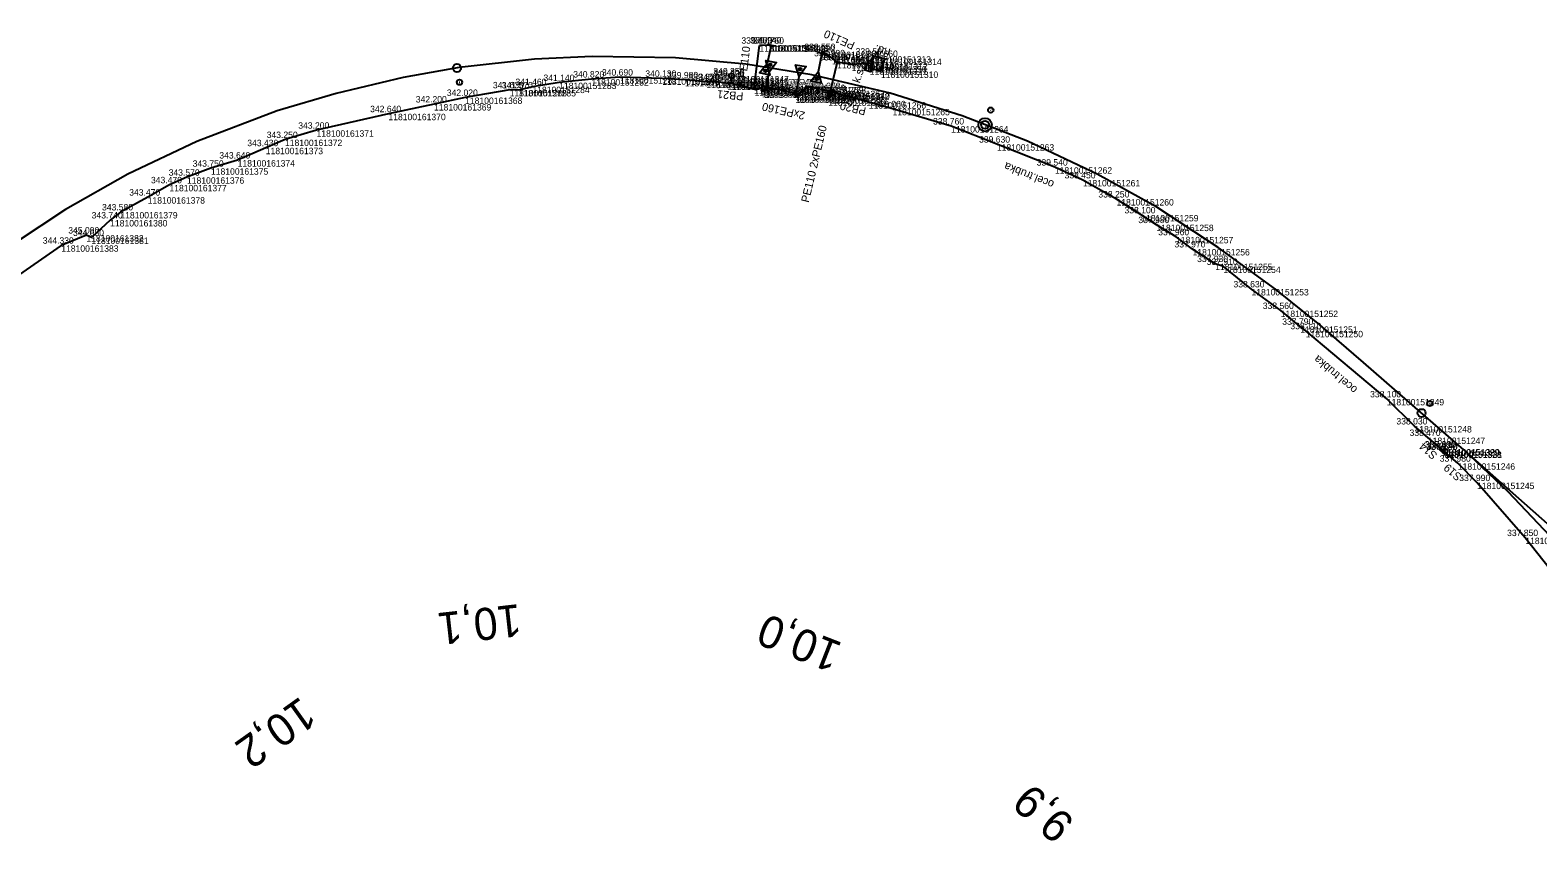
# Model space of a CAD drawing. Extents: x -732194 to -724760, y -944826 to -941477.
# Drawn here: x -726586.2 to -726304.2, y -941987.6 to -941833 of the extents above; entities that cross this region are included whole.
import ezdxf

# ---------------------------------------------------------------- set-up
doc = ezdxf.new("R2010")
doc.units = 0
for name, color, linetype in [('Vrstva 1', 7, 'Continuous'), ('Vrstva 25', 7, 'Continuous'), ('Vrstva 26', 7, 'Continuous'), ('Vrstva 28', 7, 'Continuous'), ('Vrstva 31', 7, 'Continuous'), ('Vrstva 35', 7, 'Continuous'), ('Vrstva 36', 7, 'Continuous'), ('Vrstva 4', 7, 'Continuous'), ('Vrstva 60', 7, 'Continuous'), ('Vrstva 61', 7, 'Continuous'), ('Vrstva 7', 7, 'Continuous')]:
    doc.layers.add(name, color=color, linetype=linetype)

msp = doc.modelspace()

# ---------------------------------------------------------------- linework, layer by layer
at = {"layer": 'Vrstva 1'}
for points in [[(-726318.02, -941911.5), (-726326.6, -941904), (-726336.76, -941895.13), (-726344.93, -941888.1), (-726353.24, -941881.47), (-726363.93, -941873.67), (-726375.42, -941866.09), (-726386.59, -941859.91), (-726399.6, -941853.79), (-726411.82, -941849.03), (-726425.29, -941844.79), (-726440, -941841.35), (-726452.29, -941839.39), (-726465.45, -941838.18), (-726481.04, -941837.9), (-726491.84, -941838.43), (-726505.92, -941840.01), (-726516.42, -941841.85), (-726528.96, -941844.82), (-726540.03, -941848.12), (-726555, -941853.8), (-726567.96, -941859.94), (-726579.57, -941866.53), (-726589.02, -941872.75)], [(-726075.63, -942130.21), (-726101.92, -942107.27), (-726129.96, -942082.52), (-726165.94, -942050.65), (-726201.74, -942019.26), (-726248.07, -941978.65), (-726277.07, -941953.1), (-726291.76, -941938.6), (-726301.83, -941927.65), (-726309.68, -941919.38), (-726318.02, -941911.5), (-726300.8, -941926.68), (-726297.65, -941929.32), (-726289.24, -941936.18), (-726279.87, -941942.93), (-726261.51, -941955.72), (-726252.77, -941962.25), (-726242.17, -941969.3), (-726231.93, -941976.55), (-726224.85, -941981.79)]]:
    msp.add_lwpolyline(points, dxfattribs=at)
at = {"layer": 'Vrstva 25'}
msp.add_lwpolyline([(-726429.37, -941838.61), (-726428.42, -941838.91), (-726429.03, -941840.81), (-726429.98, -941840.51), (-726429.37, -941838.61)], dxfattribs=at)
at = {"layer": 'Vrstva 26'}
msp.add_line((-726437.04, -941844.32), (-726436.9, -941845.95), dxfattribs=at)
for points in [[(-726428.99, -941839.16), (-726432.52, -941839.43), (-726435.24, -941838.97), (-726436.9, -941845.95)], [(-726437.04, -941844.32), (-726440.53, -941843.63), (-726441.06, -941843.62), (-726441.68, -941844.44), (-726442.49, -941845.05), (-726443.08, -941844.83), (-726449.33, -941843.41), (-726449.39, -941843.91), (-726450.69, -941844.08), (-726455, -941842.98), (-726455.75, -941842.95), (-726457.73, -941842.64), (-726459.7, -941842.65), (-726463.7, -941842.31), (-726467.96, -941842.03), (-726475.87, -941841.8), (-726481.19, -941842.16), (-726487.24, -941842.81), (-726492.25, -941843.57), (-726494.81, -941844.2), (-726496.5, -941844.18), (-726504.84, -941845.6), (-726510.65, -941846.83), (-726519.18, -941848.64), (-726532.63, -941851.73), (-726538.53, -941853.47), (-726542.13, -941855), (-726547.39, -941857.31), (-726552.38, -941858.84), (-726556.87, -941860.52), (-726560.15, -941861.94), (-726564.22, -941864.24), (-726569.33, -941867.02), (-726571.24, -941868.52), (-726574.75, -941871.78), (-726575.69, -941871.34), (-726580.39, -941873.25), (-726599.3, -941886.4)]]:
    msp.add_lwpolyline(points, dxfattribs=at)
at = {"layer": 'Vrstva 28'}
for p, q in [((-726455.03, -941841.57), (-726454.93, -941841.57)), ((-726450.78, -941843.7), (-726450.69, -941844.08)), ((-726437.04, -941844.32), (-726436.9, -941845.95)), ((-726436.13, -941844.68), (-726436.03, -941844.7)), ((-726322, -941911.32), (-726321.92, -941911.38)), ((-726321.53, -941911.75), (-726321.61, -941911.84)), ((-726321.57, -941911.72), (-726321.49, -941911.78))]:
    msp.add_line(p, q, dxfattribs=at)
for points in [[(-726450.78, -941843.7), (-726449.77, -941835.84)], [(-726447.59, -941835.85), (-726448.11, -941835.78), (-726449.77, -941835.84)], [(-726438.08, -941837.37), (-726438.01, -941837.02), (-726436.22, -941838.19), (-726435.24, -941838.97)], [(-726428.99, -941839.16), (-726432.52, -941839.43), (-726435.24, -941838.97), (-726436.9, -941845.95)], [(-726437.04, -941844.32), (-726440.53, -941843.63), (-726441.06, -941843.62), (-726441.68, -941844.44), (-726442.49, -941845.05), (-726443.08, -941844.83), (-726449.33, -941843.41), (-726449.39, -941843.91), (-726450.69, -941844.08), (-726455, -941842.98), (-726455.75, -941842.95), (-726457.73, -941842.64), (-726459.7, -941842.65), (-726463.7, -941842.31), (-726467.96, -941842.03), (-726475.87, -941841.8), (-726481.19, -941842.16), (-726487.24, -941842.81), (-726492.25, -941843.57), (-726494.81, -941844.2), (-726496.5, -941844.18), (-726504.84, -941845.6), (-726510.65, -941846.83), (-726519.18, -941848.64), (-726532.63, -941851.73), (-726538.53, -941853.47), (-726542.13, -941855), (-726547.39, -941857.31), (-726552.38, -941858.84), (-726556.87, -941860.52), (-726560.15, -941861.94), (-726564.22, -941864.24), (-726569.33, -941867.02), (-726571.24, -941868.52), (-726574.75, -941871.78), (-726575.69, -941871.34), (-726580.39, -941873.25), (-726599.3, -941886.4)], [(-726455, -941842.98), (-726455.04, -941842.21), (-726454.99, -941841.92), (-726454.98, -941841.57)], [(-726448.57, -941844.25), (-726448.83, -941844.48), (-726449.29, -941844.35), (-726449.39, -941843.91)], [(-726442.49, -941845.05), (-726442.62, -941845.32), (-726443.05, -941845.4), (-726442.89, -941845.07)], [(-726300.83, -941935.1), (-726306.5, -941927.93), (-726315.51, -941917.64), (-726319.12, -941914.01), (-726321.61, -941911.84), (-726322.08, -941911.41), (-726324.72, -941909.2), (-726327.22, -941907.05), (-726332.4, -941901.98), (-726347.57, -941889.24), (-726348.59, -941888.41), (-726352.24, -941885.45), (-726357.72, -941881.42), (-726362.98, -941877.21), (-726364.51, -941876.68), (-726368.75, -941873.94), (-726371.83, -941871.66), (-726375.51, -941869.39), (-726378.35, -941867.57), (-726382.97, -941864.6), (-726389.26, -941861.03), (-726394.51, -941858.63), (-726405.35, -941854.33), (-726413.91, -941850.95), (-726424.87, -941847.72), (-726429.31, -941846.47), (-726437.04, -941844.32)], [(-726436.9, -941845.95), (-726436.41, -941845.56), (-726436.19, -941844.83), (-726436.08, -941844.69)], [(-726322.08, -941911.41), (-726321.96, -941911.35)]]:
    msp.add_lwpolyline(points, dxfattribs=at)
for centre in [(-726454.98, -941841.57), (-726436.08, -941844.69), (-726321.96, -941911.35), (-726321.53, -941911.75)]:
    msp.add_circle(centre, 0.5, dxfattribs=at)
at = {"layer": 'Vrstva 31'}
for points in [[(-726437.04, -941844.32), (-726440.53, -941843.63), (-726441.06, -941843.62), (-726441.68, -941844.44), (-726442.49, -941845.05), (-726443.08, -941844.83), (-726449.33, -941843.41), (-726449.39, -941843.91), (-726450.69, -941844.08), (-726455, -941842.98), (-726455.75, -941842.95), (-726457.73, -941842.64), (-726459.7, -941842.65), (-726463.7, -941842.31), (-726467.96, -941842.03), (-726475.87, -941841.8), (-726481.19, -941842.16), (-726487.24, -941842.81), (-726492.25, -941843.57), (-726494.81, -941844.2), (-726496.5, -941844.18), (-726504.84, -941845.6), (-726510.65, -941846.83), (-726519.18, -941848.64), (-726532.63, -941851.73), (-726538.53, -941853.47), (-726542.13, -941855), (-726547.39, -941857.31), (-726552.38, -941858.84), (-726556.87, -941860.52), (-726560.15, -941861.94), (-726564.22, -941864.24), (-726569.33, -941867.02), (-726571.24, -941868.52), (-726574.75, -941871.78), (-726575.69, -941871.34), (-726580.39, -941873.25), (-726599.3, -941886.4)], [(-726300.83, -941935.1), (-726306.5, -941927.93), (-726315.51, -941917.64), (-726319.12, -941914.01), (-726321.61, -941911.84), (-726322.08, -941911.41), (-726324.72, -941909.2), (-726327.22, -941907.05), (-726332.4, -941901.98), (-726347.57, -941889.24), (-726348.59, -941888.41), (-726352.24, -941885.45), (-726357.72, -941881.42), (-726362.98, -941877.21), (-726364.51, -941876.68), (-726368.75, -941873.94), (-726371.83, -941871.66), (-726375.51, -941869.39), (-726378.35, -941867.57), (-726382.97, -941864.6), (-726389.26, -941861.03), (-726394.51, -941858.63), (-726405.35, -941854.33), (-726413.91, -941850.95), (-726424.87, -941847.72), (-726429.31, -941846.47), (-726437.04, -941844.32)]]:
    msp.add_lwpolyline(points, dxfattribs=at)
at = {"layer": 'Vrstva 35'}
for points in [[(-726450.78, -941843.7), (-726449.77, -941835.84)], [(-726435.24, -941838.97), (-726436.22, -941838.19), (-726438.08, -941837.37)], [(-726435.24, -941838.97), (-726436.9, -941845.95)], [(-726443.08, -941844.83), (-726449.33, -941843.41)], [(-726394.51, -941858.63), (-726405.35, -941854.33)], [(-726332.4, -941901.98), (-726347.57, -941889.24)]]:
    msp.add_lwpolyline(points, dxfattribs=at)
at = {"layer": 'Vrstva 36'}
msp.add_lwpolyline([(-726427.04, -941840.73), (-726429.13, -941840.12), (-726428.41, -941837.87), (-726426.38, -941838.31), (-726427.04, -941840.73)], dxfattribs=at)
at = {"layer": 'Vrstva 4'}
for p, q in [((-726446.83, -941836.02), (-726448.35, -941835.68)), ((-726437.32, -941837.53), (-726438.84, -941837.21)), ((-726448.42, -941840.45), (-726448.84, -941840.71)), ((-726447.95, -941839.62), (-726447.54, -941839.34)), ((-726442.36, -941840.43), (-726441.96, -941840.14)), ((-726438.83, -941841.98), (-726439.24, -941842.25)), ((-726449.34, -941844.11), (-726447.8, -941844.39)), ((-726443.66, -941844.95), (-726442.12, -941845.19))]:
    msp.add_line(p, q, dxfattribs=at)
for points in [[(-726447.59, -941835.85), (-726448.36, -941839.24), (-726447.84, -941841.42), (-726449.79, -941840.98), (-726448.36, -941839.24)], [(-726438.08, -941837.37), (-726438.78, -941840.77), (-726438.22, -941842.94), (-726440.18, -941842.54), (-726438.78, -941840.77)], [(-726448.57, -941844.25), (-726447.95, -941840.83), (-726448.57, -941838.68), (-726446.6, -941839.03), (-726447.95, -941840.83)], [(-726442.89, -941845.07), (-726442.34, -941841.64), (-726443, -941839.5), (-726441.03, -941839.81), (-726442.34, -941841.64)]]:
    msp.add_lwpolyline(points, dxfattribs=at)
for centre in [(-726448.63, -941840.58), (-726447.74, -941839.48), (-726442.16, -941840.29), (-726439.03, -941842.12)]:
    msp.add_circle(centre, 0.248, dxfattribs=at)
at = {"layer": 'Vrstva 60'}
for p, q in [((-726449.77, -941835.84), (-726449.77, -941835.84)), ((-726448.11, -941835.78), (-726448.11, -941835.78)), ((-726447.59, -941835.85), (-726447.59, -941835.85)), ((-726438.08, -941837.37), (-726438.08, -941837.37)), ((-726438.01, -941837.02), (-726438.01, -941837.02)), ((-726436.22, -941838.19), (-726436.22, -941838.19)), ((-726435.24, -941838.97), (-726435.24, -941838.97)), ((-726432.52, -941839.43), (-726432.52, -941839.43)), ((-726429.2, -941839.71), (-726429.2, -941839.71)), ((-726429.13, -941840.12), (-726429.13, -941840.12)), ((-726428.99, -941839.16), (-726428.99, -941839.16)), ((-726428.41, -941837.87), (-726428.41, -941837.87)), ((-726426.38, -941838.31), (-726426.38, -941838.31)), ((-726487.24, -941842.81), (-726487.24, -941842.81)), ((-726481.19, -941842.16), (-726481.19, -941842.16)), ((-726475.87, -941841.8), (-726475.87, -941841.8)), ((-726467.96, -941842.03), (-726467.96, -941842.03)), ((-726463.7, -941842.31), (-726463.7, -941842.31)), ((-726459.7, -941842.65), (-726459.7, -941842.65)), ((-726457.73, -941842.64), (-726457.73, -941842.64)), ((-726455.75, -941842.95), (-726455.75, -941842.95)), ((-726455.04, -941842.21), (-726455.04, -941842.21)), ((-726455, -941842.98), (-726455, -941842.98)), ((-726454.99, -941841.92), (-726454.99, -941841.92)), ((-726454.98, -941841.57), (-726454.98, -941841.57)), ((-726427.04, -941840.73), (-726427.04, -941840.73)), ((-726504.84, -941845.6), (-726504.84, -941845.6)), ((-726496.5, -941844.18), (-726496.5, -941844.18)), ((-726494.81, -941844.2), (-726494.81, -941844.2)), ((-726492.25, -941843.57), (-726492.25, -941843.57)), ((-726450.78, -941843.7), (-726450.78, -941843.7)), ((-726450.69, -941844.08), (-726450.69, -941844.08)), ((-726449.39, -941843.91), (-726449.39, -941843.91)), ((-726449.33, -941843.41), (-726449.33, -941843.41)), ((-726449.29, -941844.35), (-726449.29, -941844.35)), ((-726448.83, -941844.48), (-726448.83, -941844.48)), ((-726448.57, -941844.25), (-726448.57, -941844.25)), ((-726443.08, -941844.83), (-726443.08, -941844.83)), ((-726443.05, -941845.4), (-726443.05, -941845.4)), ((-726442.89, -941845.07), (-726442.89, -941845.07)), ((-726442.62, -941845.32), (-726442.62, -941845.32)), ((-726442.49, -941845.05), (-726442.49, -941845.05)), ((-726441.68, -941844.44), (-726441.68, -941844.44)), ((-726441.06, -941843.62), (-726441.06, -941843.62)), ((-726440.53, -941843.63), (-726440.53, -941843.63)), ((-726437.04, -941844.32), (-726437.04, -941844.32)), ((-726436.9, -941845.95), (-726436.9, -941845.95)), ((-726436.41, -941845.56), (-726436.41, -941845.56)), ((-726436.19, -941844.83), (-726436.19, -941844.83)), ((-726436.08, -941844.69), (-726436.08, -941844.69)), ((-726519.18, -941848.64), (-726519.18, -941848.64)), ((-726510.65, -941846.83), (-726510.65, -941846.83)), ((-726429.31, -941846.47), (-726429.31, -941846.47)), ((-726424.87, -941847.72), (-726424.87, -941847.72)), ((-726532.63, -941851.73), (-726532.63, -941851.73)), ((-726413.91, -941850.95), (-726413.91, -941850.95)), ((-726538.53, -941853.47), (-726538.53, -941853.47)), ((-726405.35, -941854.33), (-726405.35, -941854.33)), ((-726547.39, -941857.31), (-726547.39, -941857.31)), ((-726542.13, -941855), (-726542.13, -941855)), ((-726552.38, -941858.84), (-726552.38, -941858.84)), ((-726394.51, -941858.63), (-726394.51, -941858.63)), ((-726560.15, -941861.94), (-726560.15, -941861.94)), ((-726556.87, -941860.52), (-726556.87, -941860.52)), ((-726389.26, -941861.03), (-726389.26, -941861.03)), ((-726564.22, -941864.24), (-726564.22, -941864.24)), ((-726382.97, -941864.6), (-726382.97, -941864.6)), ((-726571.24, -941868.52), (-726571.24, -941868.52)), ((-726569.33, -941867.02), (-726569.33, -941867.02)), ((-726378.35, -941867.57), (-726378.35, -941867.57)), ((-726575.69, -941871.34), (-726575.69, -941871.34)), ((-726375.51, -941869.39), (-726375.51, -941869.39)), ((-726580.39, -941873.25), (-726580.39, -941873.25)), ((-726574.75, -941871.78), (-726574.75, -941871.78)), ((-726371.83, -941871.66), (-726371.83, -941871.66)), ((-726368.75, -941873.94), (-726368.75, -941873.94)), ((-726364.51, -941876.68), (-726364.51, -941876.68)), ((-726362.98, -941877.21), (-726362.98, -941877.21)), ((-726357.72, -941881.42), (-726357.72, -941881.42)), ((-726352.24, -941885.45), (-726352.24, -941885.45)), ((-726348.59, -941888.41), (-726348.59, -941888.41)), ((-726347.57, -941889.24), (-726347.57, -941889.24)), ((-726332.4, -941901.98), (-726332.4, -941901.98)), ((-726327.22, -941907.05), (-726327.22, -941907.05)), ((-726324.72, -941909.2), (-726324.72, -941909.2)), ((-726322.08, -941911.41), (-726322.08, -941911.41)), ((-726321.96, -941911.35), (-726321.96, -941911.35)), ((-726321.61, -941911.84), (-726321.61, -941911.84)), ((-726321.53, -941911.75), (-726321.53, -941911.75)), ((-726319.12, -941914.01), (-726319.12, -941914.01)), ((-726315.51, -941917.64), (-726315.51, -941917.64)), ((-726306.5, -941927.93), (-726306.5, -941927.93))]:
    msp.add_line(p, q, dxfattribs=at)
at = {"layer": 'Vrstva 7'}
for p, q in [((-726505.94, -941842.74), (-726505.84, -941842.73)), ((-726406.55, -941847.93), (-726406.46, -941847.97)), ((-726324.39, -941902.8), (-726324.31, -941902.86))]:
    msp.add_line(p, q, dxfattribs=at)
for centre, radius in [((-726506.36, -941840.08), 0.75), ((-726505.89, -941842.74), 0.5), ((-726406.51, -941847.95), 0.5), ((-726407.57, -941850.69), 1.25), ((-726407.57, -941850.69), 0.752), ((-726324.35, -941902.83), 0.5), ((-726325.9, -941904.61), 0.75)]:
    msp.add_circle(centre, radius, dxfattribs=at)

# ---------------------------------------------------------------- texts
at = {"layer": 'Vrstva 25'}
msp.add_text('k.s.', height=1.5, rotation=72.2553, dxfattribs=at).set_placement((-726431.01, -941842.99))
at = {"layer": 'Vrstva 28'}
for s, rotation, p in [('PB21', 174.7314, (-726452.72, -941844.67)), ('PB20', 166.8492, (-726429.72, -941847.49)), ('S14', 138.8684, (-726322.83, -941912.32)), ('S19', 138.8684, (-726318.25, -941916.32))]:
    msp.add_text(s, height=1.5, rotation=rotation, dxfattribs=at).set_placement(p)
at = {"layer": 'Vrstva 36'}
for s, rotation, p in [('PE110', 156.2092, (-726431.79, -941835.32)), ('PE110', 82.696, (-726452.24, -941842.08)), ('r.d.', 163.7293, (-726425.17, -941836.53)), ('2xPE160', 167.1997, (-726441.14, -941848.33)), ('PE110 2xPE160', 76.6223, (-726440.55, -941865.34)), ('ocel.trubka', 158.3628, (-726394.52, -941861.3)), ('ocel.trubka', 139.9759, (-726337.78, -941900.01))]:
    msp.add_text(s, height=1.5, rotation=rotation, dxfattribs=at).set_placement(p)
at = {"layer": 'Vrstva 60'}
for s, p in [('118100151327', (-726449.77, -941837.04)), ('118100151349', (-726448.11, -941836.98)), ('118100151348', (-726447.59, -941837.05)), ('118100151319', (-726438.08, -941838.57)), ('118100151318', (-726438.01, -941838.22)), ('118100151317', (-726436.22, -941839.39)), ('118100151316', (-726435.24, -941840.17)), ('118100151315', (-726432.52, -941840.63)), ('118100151350', (-726429.2, -941840.91)), ('118100151311', (-726429.13, -941841.32)), ('118100151312', (-726428.99, -941840.36)), ('118100151313', (-726428.41, -941839.07)), ('118100151314', (-726426.38, -941839.51)), ('118100151283', (-726487.24, -941844.01)), ('118100151282', (-726481.19, -941843.36)), ('118100151281', (-726475.87, -941843)), ('118100151280', (-726467.96, -941843.23)), ('118100151279', (-726463.7, -941843.51)), ('118100151278', (-726459.7, -941843.85)), ('118100151277', (-726457.73, -941843.84)), ('118100151276', (-726455.75, -941844.15)), ('118100151345', (-726455.04, -941843.41)), ('118100151344', (-726455, -941844.18)), ('118100151346', (-726454.99, -941843.12)), ('118100151347', (-726454.98, -941842.77)), ('118100151310', (-726427.04, -941841.93)), ('118100161368', (-726504.84, -941846.8)), ('118100151286', (-726496.5, -941845.38)), ('118100151285', (-726494.81, -941845.4)), ('118100151284', (-726492.25, -941844.77)), ('118100151326', (-726450.78, -941844.9)), ('118100151275', (-726450.69, -941845.28)), ('118100151274', (-726449.39, -941845.11)), ('118100151273', (-726449.33, -941844.61)), ('118100151343', (-726449.29, -941845.55)), ('118100151342', (-726448.83, -941845.68)), ('118100151341', (-726448.57, -941845.45)), ('118100151272', (-726443.08, -941846.03)), ('118100151324', (-726443.05, -941846.6)), ('118100151325', (-726442.89, -941846.27)), ('118100151323', (-726442.62, -941846.52)), ('118100151271', (-726442.49, -941846.25)), ('118100151270', (-726441.68, -941845.64)), ('118100151269', (-726441.06, -941844.82)), ('118100151268', (-726440.53, -941844.83)), ('118100151267', (-726437.04, -941845.52)), ('118100151320', (-726436.9, -941847.15)), ('118100151321', (-726436.41, -941846.76)), ('118100151322', (-726436.19, -941846.03)), ('118100151340', (-726436.08, -941845.89)), ('118100161370', (-726519.18, -941849.84)), ('118100161369', (-726510.65, -941848.03)), ('118100151266', (-726429.31, -941847.67)), ('118100151265', (-726424.87, -941848.92)), ('118100161371', (-726532.63, -941852.93)), ('118100151264', (-726413.91, -941852.15)), ('118100161372', (-726538.53, -941854.67)), ('118100151263', (-726405.35, -941855.53)), ('118100161374', (-726547.39, -941858.51)), ('118100161373', (-726542.13, -941856.2)), ('118100161375', (-726552.38, -941860.04)), ('118100151262', (-726394.51, -941859.83)), ('118100161377', (-726560.15, -941863.14)), ('118100161376', (-726556.87, -941861.72)), ('118100151261', (-726389.26, -941862.23)), ('118100161378', (-726564.22, -941865.44)), ('118100151260', (-726382.97, -941865.8)), ('118100161380', (-726571.24, -941869.72)), ('118100161379', (-726569.33, -941868.22)), ('118100151259', (-726378.35, -941868.77)), ('118100161382', (-726575.69, -941872.54)), ('118100151258', (-726375.51, -941870.59)), ('118100161383', (-726580.39, -941874.45)), ('118100161381', (-726574.75, -941872.98)), ('118100151257', (-726371.83, -941872.86)), ('118100151256', (-726368.75, -941875.14)), ('118100151255', (-726364.51, -941877.88)), ('118100151254', (-726362.98, -941878.41)), ('118100151253', (-726357.72, -941882.62)), ('118100151252', (-726352.24, -941886.65)), ('118100151251', (-726348.59, -941889.61)), ('118100151250', (-726347.57, -941890.44)), ('118100151249', (-726332.4, -941903.18)), ('118100151248', (-726327.22, -941908.25)), ('118100151247', (-726324.72, -941910.4)), ('118100151329', (-726322.08, -941912.61)), ('118100151330', (-726321.96, -941912.55)), ('118100151328', (-726321.61, -941913.04)), ('118100151331', (-726321.53, -941912.95)), ('118100151246', (-726319.12, -941915.21)), ('118100151245', (-726315.51, -941918.84)), ('118100151244', (-726306.5, -941929.13))]:
    msp.add_text(s, height=1.2, dxfattribs=at).set_placement(p)
at = {"layer": 'Vrstva 61'}
for s, p in [('339.870', (-726453.15, -941835.54)), ('339.940', (-726451.48, -941835.48)), ('340.760', (-726450.99, -941835.55)), ('340.250', (-726441.5, -941837.07)), ('339.550', (-726441.38, -941836.72)), ('338.990', (-726439.56, -941837.89)), ('338.630', (-726438.61, -941838.67)), ('339.500', (-726431.78, -941837.57)), ('339.660', (-726429.69, -941838.01)), ('340.690', (-726479.24, -941841.5)), ('340.350', (-726458.4, -941841.27)), ('339.220', (-726458.36, -941841.62)), ('338.690', (-726435.86, -941839.13)), ('339.450', (-726432.6, -941839.41)), ('339.530', (-726432.5, -941839.82)), ('338.710', (-726432.13, -941838.86)), ('339.640', (-726430.41, -941840.43)), ('341.630', (-726499.64, -941843.88)), ('341.570', (-726497.98, -941843.9)), ('341.460', (-726495.42, -941843.27)), ('341.140', (-726490.18, -941842.51)), ('340.820', (-726484.61, -941841.86)), ('340.130', (-726471.12, -941841.73)), ('339.980', (-726467.04, -941842.01)), ('339.830', (-726463.07, -941842.35)), ('340.020', (-726461.15, -941842.34)), ('339.740', (-726459.15, -941842.65)), ('339.250', (-726458.41, -941841.91)), ('339.680', (-726458.34, -941842.68)), ('339.380', (-726454.15, -941843.4)), ('339.580', (-726454.06, -941843.78)), ('340.430', (-726452.84, -941843.61)), ('340.380', (-726452.75, -941843.11)), ('339.710', (-726452.41, -941844.05)), ('339.720', (-726452.21, -941844.18)), ('340.670', (-726451.97, -941843.95)), ('339.040', (-726445.07, -941844.14)), ('339.400', (-726444.45, -941843.32)), ('339.300', (-726443.9, -941843.33)), ('339.270', (-726440.42, -941844.02)), ('340.230', (-726439.5, -941844.39)), ('342.200', (-726514.07, -941846.53)), ('342.020', (-726508.26, -941845.3)), ('339.630', (-726446.39, -941845.1)), ('340.480', (-726446.34, -941844.77)), ('340.210', (-726446.24, -941844.53)), ('339.080', (-726445.99, -941845.02)), ('338.940', (-726445.89, -941844.75)), ('338.720', (-726440.3, -941845.65)), ('338.790', (-726439.79, -941845.26)), ('339.210', (-726439.3, -941844.53)), ('339.190', (-726432.39, -941846.17)), ('342.640', (-726522.61, -941848.34)), ('339.060', (-726428.21, -941847.42)), ('343.200', (-726536.05, -941851.43)), ('338.760', (-726417.29, -941850.65)), ('343.430', (-726545.59, -941854.7)), ('343.250', (-726541.96, -941853.17)), ('339.630', (-726408.69, -941854.03)), ('343.750', (-726555.81, -941858.54)), ('343.640', (-726550.82, -941857.01)), ('339.540', (-726397.91, -941858.33)), ('343.570', (-726560.3, -941860.22)), ('338.450', (-726392.69, -941860.73)), ('343.470', (-726567.68, -941863.94)), ('343.470', (-726563.61, -941861.64)), ('343.580', (-726572.76, -941866.72)), ('338.250', (-726386.37, -941864.3)), ('343.740', (-726574.7, -941868.22)), ('338.100', (-726381.48, -941867.27)), ('337.980', (-726378.89, -941869.09)), ('345.090', (-726579.08, -941871.04)), ('344.080', (-726578.2, -941871.48)), ('337.960', (-726375.18, -941871.36)), ('344.330', (-726583.85, -941872.95)), ('337.970', (-726372.13, -941873.64)), ('337.930', (-726367.89, -941876.38)), ('337.910', (-726366.1, -941876.91)), ('338.630', (-726361.09, -941881.12)), ('338.560', (-726355.61, -941885.15)), ('337.790', (-726351.97, -941888.11)), ('338.110', (-726350.45, -941888.94)), ('338.100', (-726335.53, -941901.68)), ('338.030', (-726330.61, -941906.75)), ('338.470', (-726328.15, -941908.9)), ('338.690', (-726325.3, -941911.05)), ('337.810', (-726325.22, -941911.11)), ('337.780', (-726325.02, -941911.54)), ('338.640', (-726324.93, -941911.45)), ('337.980', (-726322.5, -941913.71)), ('337.990', (-726318.86, -941917.34)), ('337.850', (-726309.9, -941927.63))]:
    msp.add_text(s, height=1.2, dxfattribs=at).set_placement(p)
at = {"layer": 'Vrstva 7'}
for s, rotation, p in [('10,1', 186.3813, (-726494.68, -941940.32)), ('10,0', 158.7022, (-726434, -941947.71)), ('10,2', 215.5128, (-726535.6, -941957.47)), ('9,9', 138.8684, (-726390.51, -941980.95))]:
    msp.add_text(s, height=6, rotation=rotation, dxfattribs=at).set_placement(p)

doc.saveas('drawing.dxf')
